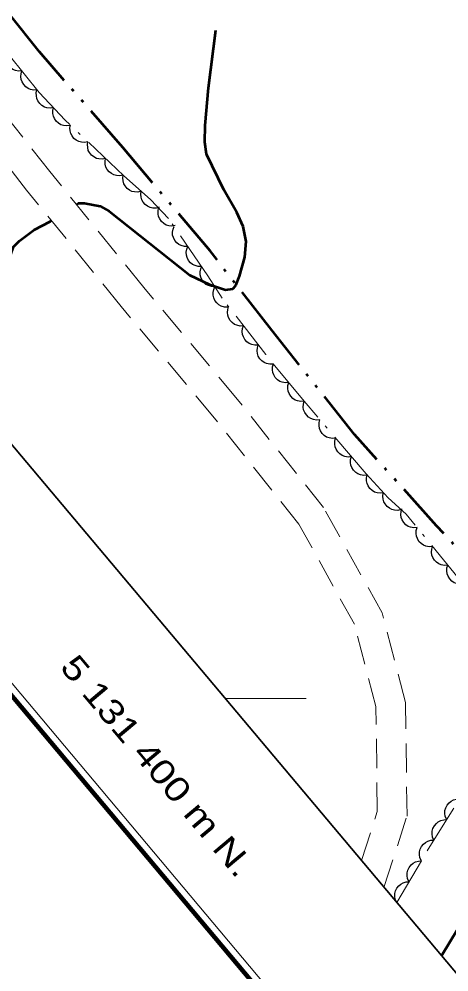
# Model space of a CAD drawing. Extents: x 386081 to 389416, y 5130568 to 5134082.
# Drawn here: x 387416.1 to 387469.2, y 5131366.2 to 5131484.2 of the extents above; entities that cross this region are included whole.
import ezdxf
from ezdxf.enums import TextEntityAlignment as Align

# ---------------------------------------------------------------- set-up
doc = ezdxf.new("R2010")
doc.units = 0
doc.header["$LTSCALE"] = 1.2
for name, pattern in [('DASH_DOUBLE_DOT', [9.2, 5, -1.2, 0.3, -1.2, 0.3, -1.2]), ('DOT_DASHED', [7.7, 5, -1.2, 0.3, -1.2]), ('LONG_DASHED', [7.5, 6, -1.5]), ('MEDIUM_DASHED', [4.5, 3, -1.5])]:
    doc.linetypes.add(name, pattern=pattern)
for name, color, linetype, lineweight in [('1', 7, 'Continuous', 53), ('19', 7, 'Continuous', 13), ('4', 7, 'DASH_DOUBLE_DOT', 53), ('44', 7, 'Continuous', 25), ('60', 7, 'Continuous', 13), ('61', 7, 'Continuous', 13)]:
    doc.layers.add(name, color=color, linetype=linetype, lineweight=lineweight)

msp = doc.modelspace()

# ---------------------------------------------------------------- linework, layer by layer
at = {"layer": '1', "linetype": 'LONG_DASHED'}
msp.add_lwpolyline([(387439.64, 5131451.3), (387441.59, 5131450.62), (387442.51, 5131450.74), (387442.87, 5131451.18), (387443.35, 5131452.34), (387443.98, 5131454.68), (387444.14, 5131456.63), (387443.77, 5131458.48), (387442.99, 5131460.22), (387441.38, 5131463.01), (387439.24, 5131467.44), (387439.03, 5131468.92), (387439.07, 5131470.99), (387439.5, 5131475.66), (387440.64, 5131484.55)], dxfattribs=at)
at = {"layer": '1'}
for points in [[(387423.15, 5131461.22), (387423.42, 5131461.37), (387424.14, 5131461.37), (387426.08, 5131460.99), (387427.19, 5131460.4), (387437.19, 5131452.47), (387439.64, 5131451.3)], [(387408.4, 5131439.48), (387410.38, 5131441.9), (387411.52, 5131443.78), (387411.76, 5131444.94), (387412.95, 5131449.05), (387415.36, 5131455.95), (387416.11, 5131456.72), (387417.91, 5131458.07), (387419.92, 5131459.11), (387420.05, 5131459.22)]]:
    msp.add_lwpolyline(points, dxfattribs=at)
at = {"layer": '19', "linetype": 'MEDIUM_DASHED'}
for points in [[(387461.2, 5131376.62), (387464.06, 5131385.46), (387463.88, 5131399.53), (387460.98, 5131410.61), (387453.74, 5131423.66), (387443.09, 5131437.07), (387431.51, 5131450.92), (387419.86, 5131465.28), (387409.58, 5131478.42)], [(387458.42, 5131379.94), (387460.38, 5131386.01), (387460.22, 5131399.03), (387457.55, 5131409.23), (387450.68, 5131421.61), (387440.24, 5131434.75), (387428.68, 5131448.59), (387416.99, 5131462.99), (387406.66, 5131476.2)]]:
    msp.add_lwpolyline(points, dxfattribs=at)
at = {"layer": '4'}
msp.add_lwpolyline([(387468.34, 5131368.13), (387472.99, 5131375.91), (387480.28, 5131387.7), (387485.39, 5131395.34), (387483.54, 5131396.43), (387481.05, 5131404.41), (387476.1, 5131412.34), (387467.71, 5131421.42), (387457.58, 5131432.71), (387447.33, 5131445.63), (387439.69, 5131455.46), (387428.91, 5131468.26), (387418.58, 5131480.12), (387410.21, 5131490.67), (387403.7, 5131499.66), (387399.9, 5131503.65), (387392.58, 5131510.4), (387382.26, 5131522.09), (387353.39, 5131556.26), (387344.01, 5131567.69), (387335.57, 5131577.2), (387325.04, 5131589.69), (387315.41, 5131601.26), (387311.54, 5131606.03)], dxfattribs=at)
at = {"layer": '44'}
for points in [[(387416.42, 5131477.75), (387416, 5131477.72), (387415.61, 5131477.81), (387415.29, 5131477.92), (387415.01, 5131478.13), (387414.76, 5131478.39), (387414.57, 5131478.73), (387414.44, 5131479.03), (387414.41, 5131479.38), (387414.43, 5131479.75), (387414.54, 5131480.09)], [(387418.3, 5131475.42), (387417.88, 5131475.38), (387417.48, 5131475.47), (387417.17, 5131475.58), (387416.89, 5131475.79), (387416.64, 5131476.06), (387416.45, 5131476.39), (387416.32, 5131476.69), (387416.29, 5131477.04), (387416.31, 5131477.41), (387416.42, 5131477.75)], [(387420.32, 5131473.2), (387419.91, 5131473.14), (387419.51, 5131473.19), (387419.19, 5131473.28), (387418.89, 5131473.47), (387418.62, 5131473.72), (387418.4, 5131474.04), (387418.25, 5131474.33), (387418.2, 5131474.67), (387418.19, 5131475.04), (387418.27, 5131475.4)], [(387422.37, 5131471.01), (387421.96, 5131470.94), (387421.55, 5131471), (387421.23, 5131471.09), (387420.94, 5131471.28), (387420.66, 5131471.52), (387420.45, 5131471.84), (387420.3, 5131472.13), (387420.24, 5131472.48), (387420.24, 5131472.85), (387420.32, 5131473.2)], [(387424.58, 5131468.98), (387424.17, 5131468.89), (387423.77, 5131468.92), (387423.44, 5131468.99), (387423.14, 5131469.16), (387422.85, 5131469.39), (387422.62, 5131469.7), (387422.45, 5131469.98), (387422.37, 5131470.32), (387422.35, 5131470.69), (387422.41, 5131471.05)], [(387426.75, 5131466.91), (387426.35, 5131466.82), (387425.94, 5131466.85), (387425.62, 5131466.92), (387425.31, 5131467.09), (387425.02, 5131467.32), (387424.79, 5131467.63), (387424.62, 5131467.91), (387424.55, 5131468.25), (387424.52, 5131468.62), (387424.58, 5131468.98)], [(387428.93, 5131464.85), (387428.52, 5131464.76), (387428.12, 5131464.79), (387427.79, 5131464.86), (387427.48, 5131465.03), (387427.2, 5131465.26), (387426.97, 5131465.56), (387426.8, 5131465.84), (387426.72, 5131466.19), (387426.7, 5131466.56), (387426.75, 5131466.91)], [(387431.17, 5131462.85), (387430.77, 5131462.75), (387430.36, 5131462.77), (387430.03, 5131462.82), (387429.72, 5131462.98), (387429.42, 5131463.2), (387429.18, 5131463.5), (387429.01, 5131463.78), (387428.92, 5131464.12), (387428.88, 5131464.49), (387428.93, 5131464.84)], [(387433.41, 5131460.86), (387433.01, 5131460.76), (387432.6, 5131460.77), (387432.28, 5131460.83), (387431.96, 5131460.99), (387431.67, 5131461.21), (387431.43, 5131461.51), (387431.25, 5131461.78), (387431.16, 5131462.13), (387431.12, 5131462.49), (387431.17, 5131462.85)], [(387435.39, 5131458.59), (387434.98, 5131458.52), (387434.58, 5131458.58), (387434.26, 5131458.66), (387433.96, 5131458.85), (387433.68, 5131459.09), (387433.47, 5131459.41), (387433.32, 5131459.7), (387433.25, 5131460.05), (387433.25, 5131460.42), (387433.33, 5131460.77)], [(387436.94, 5131456), (387436.52, 5131455.99), (387436.13, 5131456.11), (387435.83, 5131456.25), (387435.56, 5131456.47), (387435.33, 5131456.76), (387435.17, 5131457.11), (387435.06, 5131457.42), (387435.06, 5131457.77), (387435.11, 5131458.14), (387435.24, 5131458.47)], [(387438.64, 5131453.52), (387438.22, 5131453.52), (387437.83, 5131453.64), (387437.53, 5131453.77), (387437.26, 5131454), (387437.03, 5131454.29), (387436.87, 5131454.63), (387436.76, 5131454.94), (387436.75, 5131455.3), (387436.81, 5131455.66), (387436.94, 5131456)], [(387440.28, 5131451.02), (387439.86, 5131451.03), (387439.48, 5131451.16), (387439.18, 5131451.31), (387438.93, 5131451.55), (387438.7, 5131451.84), (387438.56, 5131452.2), (387438.46, 5131452.51), (387438.47, 5131452.86), (387438.54, 5131453.23), (387438.68, 5131453.56)], [(387441.88, 5131448.48), (387441.46, 5131448.49), (387441.08, 5131448.62), (387440.78, 5131448.77), (387440.52, 5131449.01), (387440.3, 5131449.3), (387440.15, 5131449.66), (387440.06, 5131449.97), (387440.07, 5131450.32), (387440.14, 5131450.69), (387440.28, 5131451.02)], [(387443.82, 5131446.18), (387443.4, 5131446.15), (387443.01, 5131446.24), (387442.7, 5131446.36), (387442.42, 5131446.58), (387442.17, 5131446.85), (387441.99, 5131447.19), (387441.87, 5131447.49), (387441.84, 5131447.84), (387441.87, 5131448.21), (387441.98, 5131448.55)], [(387445.66, 5131443.8), (387445.24, 5131443.78), (387444.84, 5131443.87), (387444.53, 5131443.99), (387444.26, 5131444.2), (387444, 5131444.47), (387443.82, 5131444.81), (387443.7, 5131445.11), (387443.67, 5131445.47), (387443.71, 5131445.84), (387443.82, 5131446.18)], [(387447.49, 5131441.43), (387447.07, 5131441.41), (387446.68, 5131441.5), (387446.37, 5131441.62), (387446.09, 5131441.83), (387445.84, 5131442.1), (387445.66, 5131442.44), (387445.54, 5131442.74), (387445.51, 5131443.09), (387445.54, 5131443.46), (387445.66, 5131443.8)], [(387449.43, 5131439.14), (387449.02, 5131439.1), (387448.62, 5131439.19), (387448.31, 5131439.29), (387448.02, 5131439.5), (387447.76, 5131439.76), (387447.57, 5131440.1), (387447.44, 5131440.39), (387447.4, 5131440.74), (387447.42, 5131441.11), (387447.53, 5131441.46)], [(387451.34, 5131436.83), (387450.92, 5131436.79), (387450.53, 5131436.87), (387450.21, 5131436.98), (387449.93, 5131437.18), (387449.67, 5131437.45), (387449.48, 5131437.78), (387449.35, 5131438.08), (387449.31, 5131438.43), (387449.33, 5131438.8), (387449.43, 5131439.14)], [(387453.29, 5131434.54), (387452.87, 5131434.5), (387452.47, 5131434.57), (387452.16, 5131434.68), (387451.87, 5131434.88), (387451.61, 5131435.14), (387451.41, 5131435.46), (387451.27, 5131435.76), (387451.23, 5131436.11), (387451.24, 5131436.48), (387451.34, 5131436.83)], [(387455.23, 5131432.26), (387454.82, 5131432.22), (387454.42, 5131432.29), (387454.1, 5131432.39), (387453.81, 5131432.59), (387453.55, 5131432.85), (387453.35, 5131433.18), (387453.22, 5131433.48), (387453.17, 5131433.83), (387453.19, 5131434.2), (387453.29, 5131434.54)], [(387457.18, 5131429.98), (387456.76, 5131429.93), (387456.36, 5131430.01), (387456.05, 5131430.11), (387455.76, 5131430.31), (387455.5, 5131430.57), (387455.3, 5131430.9), (387455.16, 5131431.19), (387455.12, 5131431.54), (387455.14, 5131431.91), (387455.23, 5131432.26)], [(387459.12, 5131427.69), (387458.71, 5131427.65), (387458.31, 5131427.72), (387457.99, 5131427.83), (387457.71, 5131428.03), (387457.44, 5131428.29), (387457.25, 5131428.61), (387457.11, 5131428.91), (387457.07, 5131429.26), (387457.08, 5131429.63), (387457.18, 5131429.98)], [(387461.17, 5131425.5), (387460.75, 5131425.44), (387460.35, 5131425.49), (387460.03, 5131425.58), (387459.74, 5131425.77), (387459.46, 5131426.02), (387459.25, 5131426.34), (387459.11, 5131426.63), (387459.05, 5131426.98), (387459.05, 5131427.35), (387459.13, 5131427.7)], [(387463.33, 5131423.42), (387462.92, 5131423.32), (387462.52, 5131423.35), (387462.19, 5131423.41), (387461.88, 5131423.58), (387461.59, 5131423.8), (387461.35, 5131424.11), (387461.18, 5131424.38), (387461.1, 5131424.72), (387461.07, 5131425.09), (387461.12, 5131425.45)], [(387465.31, 5131421.18), (387464.9, 5131421.14), (387464.5, 5131421.23), (387464.19, 5131421.34), (387463.9, 5131421.54), (387463.65, 5131421.81), (387463.46, 5131422.14), (387463.33, 5131422.44), (387463.29, 5131422.79), (387463.32, 5131423.16), (387463.42, 5131423.51)], [(387467.21, 5131418.86), (387466.79, 5131418.82), (387466.4, 5131418.9), (387466.09, 5131419.01), (387465.8, 5131419.22), (387465.54, 5131419.48), (387465.35, 5131419.82), (387465.22, 5131420.12), (387465.19, 5131420.47), (387465.21, 5131420.84), (387465.31, 5131421.18)], [(387469.11, 5131416.53), (387468.69, 5131416.49), (387468.29, 5131416.58), (387467.98, 5131416.69), (387467.7, 5131416.89), (387467.44, 5131417.16), (387467.25, 5131417.49), (387467.12, 5131417.79), (387467.08, 5131418.14), (387467.11, 5131418.51), (387467.21, 5131418.86)], [(387471, 5131414.21), (387470.59, 5131414.17), (387470.19, 5131414.25), (387469.88, 5131414.36), (387469.59, 5131414.57), (387469.34, 5131414.83), (387469.15, 5131415.17), (387469.02, 5131415.47), (387468.98, 5131415.82), (387469, 5131416.19), (387469.11, 5131416.53)], [(387468.97, 5131385.02), (387468.8, 5131385.4), (387468.75, 5131385.8), (387468.75, 5131386.13), (387468.85, 5131386.47), (387469.02, 5131386.8), (387469.27, 5131387.09), (387469.51, 5131387.31), (387469.83, 5131387.46), (387470.19, 5131387.55), (387470.55, 5131387.57)], [(387467.39, 5131382.47), (387467.22, 5131382.85), (387467.17, 5131383.25), (387467.17, 5131383.58), (387467.27, 5131383.92), (387467.44, 5131384.25), (387467.69, 5131384.54), (387467.93, 5131384.76), (387468.25, 5131384.91), (387468.61, 5131385), (387468.97, 5131385.02)], [(387465.84, 5131379.9), (387465.66, 5131380.28), (387465.6, 5131380.68), (387465.6, 5131381.01), (387465.69, 5131381.35), (387465.85, 5131381.68), (387466.1, 5131381.98), (387466.34, 5131382.2), (387466.65, 5131382.36), (387467.01, 5131382.46), (387467.37, 5131382.48)], [(387464.31, 5131377.32), (387464.13, 5131377.7), (387464.07, 5131378.1), (387464.07, 5131378.43), (387464.16, 5131378.77), (387464.32, 5131379.1), (387464.57, 5131379.4), (387464.81, 5131379.62), (387465.12, 5131379.77), (387465.48, 5131379.88), (387465.84, 5131379.9)], [(387462.78, 5131374.74), (387462.6, 5131375.12), (387462.54, 5131375.52), (387462.54, 5131375.85), (387462.63, 5131376.19), (387462.79, 5131376.52), (387463.04, 5131376.81), (387463.28, 5131377.04), (387463.59, 5131377.19), (387463.95, 5131377.3), (387464.31, 5131377.32)]]:
    msp.add_lwpolyline(points, dxfattribs=at)
at = {"layer": '44', "linetype": 'DOT_DASHED', "lineweight": 13}
msp.add_lwpolyline([(387462.78, 5131374.74), (387466.69, 5131381.34), (387475.08, 5131394.88), (387477.14, 5131397.46), (387479.49, 5131399.86), (387480.36, 5131401.17), (387480.22, 5131402.09), (387475.95, 5131407.3), (387473.96, 5131410.33), (387470.91, 5131414.32), (387463.97, 5131422.83), (387461.74, 5131424.88), (387459, 5131427.84), (387451.33, 5131436.84), (387446.58, 5131442.61), (387441.18, 5131449.59), (387439.43, 5131452.37), (387434.54, 5131459.49), (387432.31, 5131461.84), (387429.03, 5131464.75), (387421.76, 5131471.66), (387418.56, 5131475.09), (387414.84, 5131479.72)], dxfattribs=at)
at = {"layer": '60'}
msp.add_line((388114.02, 5130569.89), (386082.87, 5132988.02), dxfattribs=at)
at = {"layer": '60', "lineweight": 158}
msp.add_lwpolyline([(386081.46, 5132988.14), (387383.17, 5134081.54), (389415.62, 5131661.88), (388113.9, 5130568.48)], close=True, dxfattribs=at)
at = {"layer": '60', "lineweight": 35}
msp.add_lwpolyline([(386109.63, 5132985.69), (387380.72, 5134053.36), (389052.99, 5132062.51), (387781.9, 5130994.83)], close=True, dxfattribs=at)
at = {"layer": '61'}
msp.add_line((387441.57, 5131400), (387451.57, 5131400), dxfattribs=at)

# ---------------------------------------------------------------- texts
at = {"layer": '61', "width": 1.25}
msp.add_text('5 131 400 m N.', height=3, rotation=310.03, dxfattribs=at).set_placement((387432.021, 5131390.705), align=Align.CENTER)

doc.saveas('drawing.dxf')
